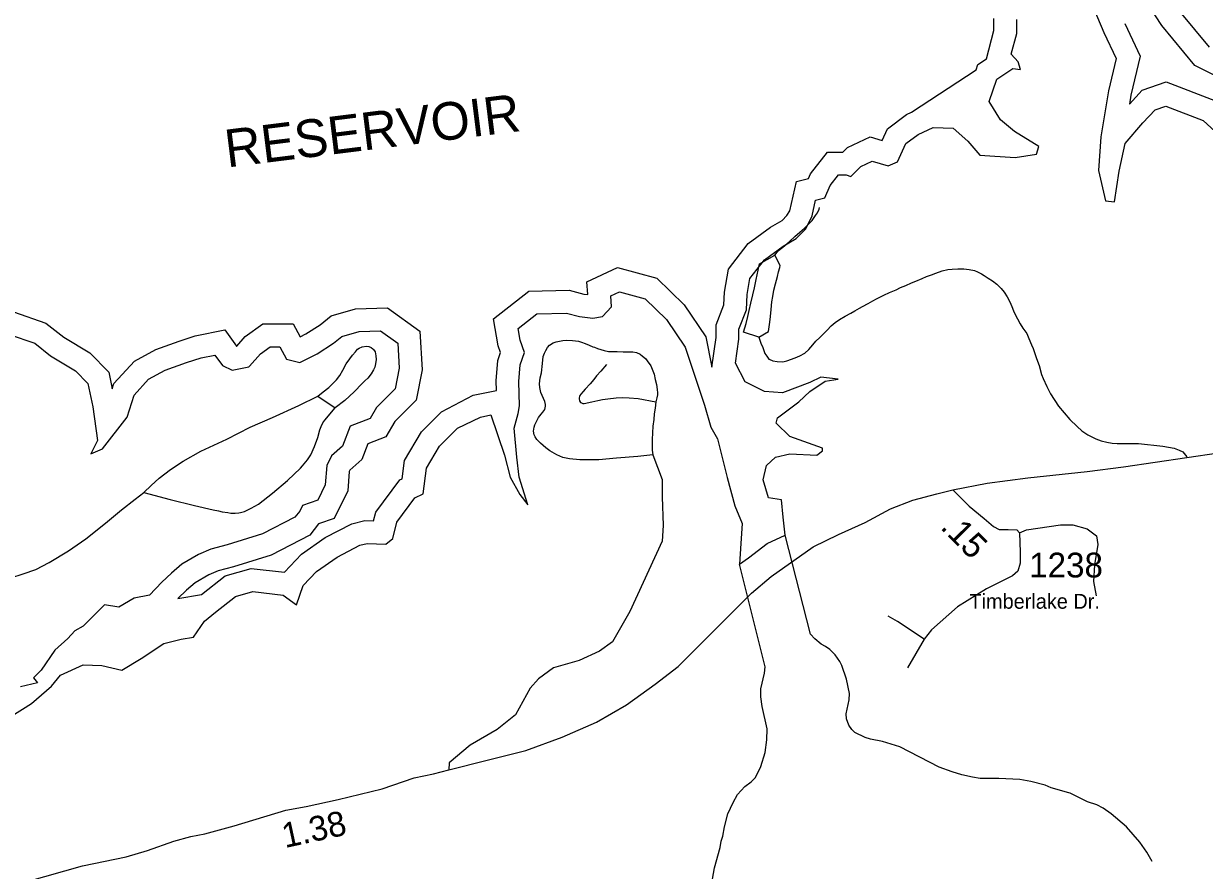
# Model space of a CAD drawing. Extents: x 1248089 to 1457196, y 820910 to 988753.
# Drawn here: x 1335904 to 1341854, y 869356 to 873625 of the extents above; entities that cross this region are included whole.
import ezdxf

# ---------------------------------------------------------------- set-up
doc = ezdxf.new("R2010")
doc.units = 0
for name, color, linetype in [('Exist Hydrographic Buffer Line', 7, 'Continuous'), ('Exist Hydrographic Misc Water Feature', 7, 'Continuous'), ('Exist Hydrographic Reservoir', 7, 'Continuous'), ('Exist Hydrographic Reservoir Label', 7, 'Continuous'), ('Exist Road Non-System Type 51', 7, 'Continuous'), ('Exist Road Primary NC Attributed', 7, 'Continuous'), ('Exist Road Secondary Type 51 Attributed', 7, 'Continuous'), ('Exist Road Secondary Type 51 Label', 7, 'Continuous'), ('Prop CMT Slope Fill', 7, 'Continuous'), ('Prop GRAU CAT1 Cell', 7, 'Continuous'), ('Prop Lane Lines', 7, 'Continuous')]:
    doc.layers.add(name, color=color, linetype=linetype)

msp = doc.modelspace()

# ---------------------------------------------------------------- linework, layer by layer
at = {"layer": 'Exist Hydrographic Buffer Line'}
for points in [[(1341452.9, 873625.9), (1341530.6, 873460.7), (1341483.6, 873263.5), (1341476.3, 873219.4), (1341541.4, 873288.6), (1341661.7, 873331.6), (1341910.1, 873235.2), (1341964.9, 873261.2), (1341994.8, 873346.7), (1341950.9, 873342), (1341806.6, 873414.2), (1341640.6, 873615.3), (1341493.7, 873840.3)], [(1339765.2, 872681.5), (1339798.8, 872829), (1339858.8, 872844), (1339869, 872867.4), (1339954.9, 872976.8), (1340032.5, 872976.8), (1340055.6, 872999.9), (1340170.6, 873053.6), (1340231, 873036.4), (1340257.6, 873094.5), (1340352.7, 873165.9), (1340378.8, 873177.6), (1340703.7, 873392.6), (1340712.5, 873418.1), (1340756.9, 873447.7), (1340793.8, 873590.1), (1340793.8, 873650.4)], [(1338010, 871667.1), (1338169, 871751.3), (1338286.6, 871774.8), (1338285.2, 871823.8), (1338293.8, 871927.4), (1338307, 871966.8), (1338295.5, 872001.2), (1338271.6, 872136.8), (1338450, 872275.6), (1338653.7, 872280.4), (1338727, 872261.1), (1338747.2, 872258.9), (1338743.2, 872323.5), (1338897.6, 872394.8), (1339095.2, 872341.4), (1339232.9, 872208), (1339342.3, 872045.8), (1339372.4, 871892.6), (1339393.8, 872042.7), (1339393.7, 872106.9), (1339433, 872206.9), (1339435.9, 872271.7), (1339456, 872387.2), (1339556.2, 872516.1), (1339667.9, 872599), (1339726.6, 872633), (1339750.6, 872657), (1339765.2, 872681.5)], [(1335853.3, 872172.7), (1336016.5, 872115.3), (1336106.2, 872045.1), (1336237.3, 871964.9), (1336333.9, 871868.3), (1336351.1, 871784.5), (1336359.4, 871810.8), (1336462.6, 871924), (1336571, 871982.8), (1336688.3, 872024.4), (1336769.2, 872051.4), (1336917.6, 872081.1), (1336977.4, 871999.5), (1336978.5, 871999.7), (1337020.5, 872047), (1337109.6, 872110.7), (1337262.7, 872110.7), (1337298.4, 872046.5), (1337325.9, 872060.8), (1337398.9, 872106.5), (1337453.5, 872152), (1337577.5, 872186.8), (1337738.3, 872191.9), (1337901.4, 872074.4), (1337912.2, 871879.8), (1337881.7, 871727), (1337774.4, 871619.6), (1337730.4, 871541.4), (1337638.9, 871506.6), (1337608.8, 871427.2), (1337548.6, 871374.5), (1337544.5, 871366.4), (1337537.6, 871268.9), (1337468.7, 871131), (1337391.1, 871102.8), (1337346.7, 871045.6), (1337151.8, 870946.1), (1336962, 870886.5), (1336884.9, 870867.2), (1336837.2, 870846), (1336768.5, 870805.9), (1336725.9, 870768.9), (1336681.3, 870727.5), (1336800.1, 870747.1), (1336919.6, 870842), (1337050.4, 870878.7), (1337218.2, 870859.6), (1337304.4, 870950.4), (1337424.5, 871034.5), (1337557.6, 871103.1), (1337623.1, 871120.1), (1337668.2, 871118.4), (1337679.3, 871162.7), (1337799.7, 871324.9), (1337811.6, 871330.8), (1337824, 871422.6), (1337909.4, 871566.4), (1338010, 871667.1)]]:
    msp.add_lwpolyline(points, dxfattribs=at)
at = {"layer": 'Exist Hydrographic Misc Water Feature'}
for points in [[(1340583.9, 869852.8), (1340517.3, 869876.2), (1340319.7, 869978.9), (1340232.3, 870006.9), (1340172.5, 870018.4), (1340144.6, 870027), (1340093.3, 870052.2), (1340077.6, 870066.5), (1340062.1, 870089), (1340050.8, 870121.2), (1340049.3, 870145.3), (1340065, 870216.8), (1340065.7, 870248.8), (1340051.4, 870321.2), (1340026.8, 870389.7), (1340017.3, 870410), (1339994, 870442.5), (1339966.7, 870469.2), (1339945, 870485.7), (1339923.3, 870496.2), (1339891.8, 870523), (1339870.4, 870547.5), (1339741.6, 871046.3)], [(1339376.2, 869312.4), (1339385.5, 869369.2), (1339413.9, 869472.5), (1339418.7, 869504.4), (1339427.2, 869528.2), (1339436.3, 869576), (1339453.8, 869641.5), (1339479.1, 869698.9), (1339502, 869738.4), (1339538.9, 869779.5), (1339571.4, 869802.6), (1339591.9, 869824.2), (1339619.2, 869879.5), (1339640.8, 869951), (1339650.3, 870014.8), (1339651.6, 870070.7), (1339626.1, 870183.3), (1339619.2, 870231.5), (1339620.1, 870271.5), (1339637.9, 870351.1), (1339640.6, 870382.9), (1339512.1, 870900.1)], [(1341590.9, 869400.6), (1341564, 869449.2), (1341529.1, 869498.1), (1341462.8, 869575.6), (1341384.3, 869641.6), (1341344.9, 869670.5), (1341313.3, 869687.2), (1341265.7, 869702.4), (1341178.6, 869746.5), (1341170.6, 869746.7), (1341083.2, 869772.7), (1341051.5, 869785.4), (1340979.9, 869805.1), (1340924.1, 869814.4), (1340818.1, 869818.9), (1340724.1, 869819.2), (1340685.6, 869826.7), (1340631.9, 869838), (1340583.9, 869852.8)]]:
    msp.add_lwpolyline(points, dxfattribs=at)
at = {"layer": 'Exist Hydrographic Reservoir'}
for points in [[(1341297.8, 873698.8), (1341347.9, 873579.3), (1341409.5, 873448.2), (1341371, 873286.2), (1341332.5, 873054.8), (1341320.9, 872885.2), (1341355.6, 872730.9), (1341401.8, 872727), (1341425, 872881.3), (1341455.8, 873020.1), (1341544.4, 873124.2), (1341606.1, 873189.8), (1341660, 873209.1), (1341848.8, 873135.8), (1341968.3, 873027.8)], [(1341879.7, 873506), (1341733.2, 873683.4)], [(1339877.2, 872656), (1339895.1, 872734.8), (1339941.4, 872746.3), (1339968.3, 872808), (1340010.7, 872862), (1340049.3, 872862), (1340072.4, 872854.3), (1340122.5, 872904.4), (1340180.3, 872931.4), (1340261.2, 872908.3), (1340307.5, 872927.6), (1340349.8, 873020.1), (1340411.5, 873066.4), (1340488.6, 873101.1), (1340588.8, 873097.3), (1340662, 873031.7), (1340723.6, 872962.3), (1340900.9, 872950.7), (1341008.8, 872966.1), (1341020.3, 873004.7), (1340897, 873081.8), (1340827.7, 873139.7), (1340769.9, 873232.2), (1340808.4, 873344.1), (1340889.3, 873398), (1340927.9, 873394.2), (1340916.3, 873432.7), (1340881.6, 873471.3), (1340908.6, 873575.4), (1340908.6, 873644.8)], [(1338091.2, 871585.9), (1338205.9, 871641.6), (1338258.1, 871652), (1338327.7, 871450.2), (1338355.5, 871338.8), (1338404.2, 871251.8), (1338445.9, 871199.6), (1338400.7, 871338.8), (1338390.3, 871439.7), (1338376.4, 871585.9), (1338397.2, 871659), (1338403.6, 871698.8), (1338400.2, 871820.6), (1338407.1, 871904.2), (1338428, 871966.8), (1338407.1, 872029.5), (1338396.7, 872088.6), (1338490.6, 872161.7), (1338640.1, 872165.2), (1338706.2, 872147.8), (1338772.3, 872140.8), (1338821, 872147.8), (1338866.2, 872196.5), (1338862.7, 872252.2), (1338907.9, 872273.1), (1339036.6, 872238.3), (1339144.4, 872133.9), (1339238.3, 871994.7), (1339335.6, 871702.3), (1339366.9, 871591), (1339401.7, 871531.8), (1339450.4, 871336.9), (1339488.7, 871194.2), (1339526, 871105.4), (1339519, 871004.5), (1339512.1, 870900.1), (1339557.3, 870931.4), (1339651.2, 871004.5), (1339741.6, 871046.3), (1339731.2, 871136.7), (1339724.2, 871223.7), (1339658.2, 871234.2), (1339630.3, 871324.7), (1339647.7, 871397.8), (1339692.9, 871439.5), (1339766, 871456.9), (1339901.6, 871450), (1339929.4, 871470.8), (1339929.4, 871484.8), (1339766, 871543.9), (1339696.4, 871610), (1339703.4, 871637.9), (1339811.2, 871717.9), (1339866.8, 871770.1), (1339943.3, 871822.3), (1340009.4, 871832.8), (1339922.5, 871843.2), (1339866.8, 871815.4), (1339727.7, 871763.2), (1339637.3, 871770.1), (1339539.9, 871818.9), (1339491.2, 871912.8), (1339508.6, 872034.6), (1339508.6, 872085.3), (1339546.8, 872182.7), (1339550.3, 872259.3), (1339564.2, 872339.3), (1339637.2, 872433.3), (1339731.1, 872502.9), (1339797.2, 872541.1), (1339845.9, 872589.9), (1339877.2, 872656)], [(1335831.9, 872058.5), (1335960.6, 872013.3), (1336040.6, 871950.6), (1336165.8, 871874.1), (1336228.4, 871811.4), (1336252.7, 871693.1), (1336277.1, 871522.6), (1336242.3, 871456.5), (1336301.4, 871480.8), (1336426.6, 871640.9), (1336461.4, 871752.3), (1336534.4, 871832.3), (1336617.9, 871877.5), (1336725.7, 871915.8), (1336798.7, 871940.2), (1336868.3, 871954.1), (1336906.5, 871901.9), (1336955.2, 871877.5), (1337038.7, 871894.9), (1337042.1, 871898.4), (1337097.8, 871961.1), (1337146.5, 871995.9), (1337195.2, 871995.9), (1337229.9, 871933.2), (1337296, 871915.8), (1337382.9, 871961.1), (1337466.4, 872013.3), (1337508.1, 872048.1), (1337595.1, 872072.4), (1337702.9, 872075.9), (1337789.8, 872013.3), (1337796.8, 871888), (1337775.9, 871783.6), (1337682, 871689.6), (1337650.7, 871633.9), (1337549.9, 871595.7), (1337511.6, 871494.7), (1337456, 871446), (1337431.6, 871397.3), (1337424.7, 871299.8), (1337386.4, 871223.3), (1337309.9, 871195.4), (1337296, 871167.6), (1337271.7, 871136.3), (1337108.2, 871052.8), (1336930.9, 870997.1), (1336847.4, 870976.2), (1336784.8, 870948.4), (1336701.3, 870899.6), (1336649.2, 870854.4), (1336600.5, 870809.1), (1336537.9, 870743), (1336461.4, 870729.1), (1336384.9, 870683.9), (1336311.8, 870694.3), (1336287.5, 870669.9), (1336204.3, 870588), (1336162.6, 870563.7), (1336127.8, 870525.4), (1336061.7, 870466.2), (1335992.2, 870365.3), (1335953.9, 870327), (1335974.8, 870302.6), (1335887.8, 870281.8)], [(1335839.1, 870132.1), (1335943.5, 870198.2), (1336044.3, 870285.2), (1336089.5, 870340.9), (1336204.3, 870393.1), (1336298.2, 870389.7), (1336399, 870365.3), (1336496.4, 870424.5), (1336611.2, 870501), (1336698.1, 870521.9), (1336760.7, 870532.3), (1336816.4, 870612.4), (1336872, 870657.6), (1336972.9, 870737.7), (1337059.8, 870762), (1337212.8, 870744.6), (1337278.9, 870695.9), (1337313.7, 870793.3), (1337379.7, 870863), (1337484.1, 870936), (1337598.8, 870995.2), (1337635.6, 871004.7), (1337729.5, 871001.2), (1337764.3, 871029.1), (1337785.2, 871112.6), (1337875.6, 871234.4), (1337917.3, 871255.3), (1337934.7, 871384.1), (1338000.8, 871495.4), (1338091.2, 871585.9)]]:
    msp.add_lwpolyline(points, dxfattribs=at)
at = {"layer": 'Exist Road Non-System Type 51'}
msp.add_line((1337386.9, 871747.2), (1337473.7, 871687.4), dxfattribs=at)
for points in [[(1339690.3, 872457.8), (1339708.7, 872481.4), (1339739.2, 872504.8), (1339763.7, 872526.3), (1339790.2, 872551.8), (1339816.7, 872573.3), (1339839.1, 872592.9), (1339857.5, 872612.5), (1339877.9, 872632.1), (1339894.4, 872657.8), (1339904.7, 872671.6), (1339913, 872689.4), (1339915.2, 872697.4)], [(1339609.9, 872045.1), (1339532.4, 872068.7), (1339545.2, 872112.5), (1339554, 872148.3), (1339560.6, 872178.2), (1339569.3, 872216), (1339578.2, 872257.9), (1339586.9, 872293.7), (1339595.8, 872335.6), (1339606.7, 872381.4), (1339613.3, 872413.3), (1339690.3, 872457.8)], [(1339609.9, 872045.1), (1339658.5, 872072.2), (1339665.5, 872120.1), (1339668, 872148), (1339670.8, 872184), (1339675.5, 872221.9), (1339680.1, 872249.8), (1339684.7, 872281.8), (1339693.4, 872313.6), (1339704.1, 872349.4), (1339708.6, 872373.3), (1339715, 872395.2), (1339717.2, 872405.2), (1339690.3, 872457.8)], [(1339609.9, 872045.1), (1339621.2, 872008.9), (1339627, 871996.7), (1339640.3, 871962.5), (1339650, 871948.3), (1339659.7, 871934), (1339673.6, 871927.8), (1339679.6, 871925.6), (1339701.5, 871921.2), (1339729.5, 871920.6), (1339749.6, 871924.2), (1339791.9, 871939.4), (1339816.2, 871950.9), (1339840.5, 871964.4), (1339860.8, 871982), (1339881.3, 872005.6), (1339895.7, 872023.4), (1339916.1, 872043), (1339934.5, 872060.6), (1339952.9, 872080.3), (1339973.3, 872101.9), (1339993.6, 872117.5), (1340016, 872133), (1340044.3, 872150.5), (1340072.6, 872165.9), (1340092.9, 872177.5), (1340117.2, 872191), (1340131.3, 872198.7), (1340159.7, 872214.2), (1340184, 872227.7), (1340202.2, 872237.3), (1340238.6, 872256.6), (1340266.9, 872270.1), (1340301.1, 872283.4), (1340323.4, 872294.9), (1340349.6, 872304.4), (1340377.9, 872317.9), (1340400.1, 872327.4), (1340432.4, 872340.8), (1340454.6, 872350.3), (1340478.8, 872357.9), (1340501, 872367.4), (1340533.2, 872378.8), (1340561.4, 872386.2), (1340583.4, 872387.8), (1340611.5, 872389.2), (1340641.5, 872388.6), (1340669.4, 872386.1), (1340695.3, 872379.5), (1340711.2, 872373.2), (1340731, 872362.8), (1340744.9, 872354.5), (1340764.6, 872342.1), (1340786.3, 872327.7), (1340808, 872311.2), (1340829.6, 872288.8), (1340845.2, 872270.4), (1340860.8, 872248.1), (1340874.3, 872221.8), (1340883.8, 872199.6), (1340893.4, 872177.4), (1340903, 872155.2), (1340912.6, 872137), (1340926.1, 872110.7), (1340939.7, 872090.4), (1340959.1, 872062), (1340970.6, 872037.8), (1340984, 872005.5), (1340991.6, 871987.3), (1340997.3, 871971.2), (1341008.6, 871937), (1341021.9, 871900.7), (1341034.1, 871855.6), (1341042.9, 871835.9), (1341060.1, 871795.5), (1341079.4, 871759.1), (1341120.1, 871696.3), (1341176.8, 871629.1), (1341214.1, 871594.3), (1341237.7, 871571.8), (1341267.3, 871551.2), (1341306.9, 871532.4), (1341334.8, 871521.8), (1341362.6, 871515.3), (1341390.6, 871510.7), (1341414.5, 871508.2), (1341444.5, 871507.6), (1341522.6, 871508.1), (1341644.4, 871495.6), (1341702.2, 871484.5), (1341728, 871473.9), (1341745.9, 871465.6), (1341765.4, 871441.2)], [(1337386.9, 871747.2), (1337413.3, 871768.7), (1337441.8, 871790.1), (1337466.3, 871813.6), (1337480.6, 871829.4), (1337497, 871851), (1337513.6, 871878.7), (1337530.3, 871910.4), (1337547.9, 871935.3), (1337561.9, 871953.1), (1337577.2, 871969.9), (1337587.4, 871983.7), (1337595.6, 871989.5), (1337609.7, 871995.3), (1337631.8, 871998.8), (1337643.7, 871996.6), (1337655.7, 871992.3), (1337663.5, 871986.2), (1337667.5, 871982.1), (1337675.2, 871969.9), (1337678.8, 871949.9), (1337680.8, 871931.4), (1337678.3, 871909.4), (1337674, 871893.5), (1337667.7, 871879.6), (1337655.3, 871859.9), (1337638.9, 871838.2), (1337624.6, 871824.5), (1337610.3, 871810.7), (1337569.5, 871769.5), (1337522.5, 871724.5), (1337473.7, 871687.4)], [(1339075.7, 871451), (1338999.7, 871442.7), (1338891.5, 871434.8), (1338803.3, 871426.6), (1338759.3, 871425.5), (1338707.2, 871426.5), (1338655.3, 871431.6), (1338621.4, 871438.2), (1338591.7, 871450.8), (1338556.1, 871471.6), (1338536.3, 871486), (1338508.8, 871510.5), (1338491.2, 871528.9), (1338481.4, 871541.1), (1338477.6, 871551.2), (1338474, 871571.3), (1338476.4, 871591.2), (1338480.7, 871603.2), (1338499.4, 871638.8), (1338511.8, 871656.6), (1338520, 871666.4), (1338530.2, 871680.2), (1338534.6, 871696.1), (1338534.7, 871704.1), (1338531, 871720.2), (1338517.6, 871750.5), (1338509.9, 871764.7), (1338506.4, 871790.8), (1338504.8, 871808.8), (1338507.4, 871838.8), (1338513.9, 871864.7), (1338518.8, 871910.9), (1338523.3, 871946.9), (1338529.6, 871962.8), (1338535.9, 871976.7), (1338544.2, 871992.5), (1338554.5, 872004.3), (1338572.7, 872015.9), (1338588.8, 872021.6), (1338621, 872027), (1338641, 872028.6), (1338671, 872028), (1338700.9, 872023.4), (1338714.9, 872019.1), (1338734.7, 872012.7), (1338754.6, 872004.3), (1338772.4, 871995.9), (1338780.4, 871993.8), (1338796.3, 871987.4), (1338830.1, 871976.7), (1338852, 871972.3), (1338872, 871971.9), (1338896, 871971.4), (1338926, 871970.8), (1338942, 871970.5), (1338968, 871970), (1338974, 871969.8), (1338992, 871967.5), (1339011.8, 871959.1), (1339023.6, 871948.8), (1339037.4, 871936.6), (1339047.2, 871924.3), (1339065.5, 871899.3), (1339082.1, 871857.2), (1339087.6, 871831.1), (1339093.1, 871805), (1339096.6, 871780.9), (1339098.2, 871762.9), (1339098, 871752.9), (1339095.8, 871738.9), (1339089.4, 871719)], [(1338841, 871906.2), (1338812.3, 871872.7), (1338791.8, 871849.1), (1338777.4, 871831.3), (1338759, 871809.7), (1338734.4, 871782.2), (1338724.2, 871770.4), (1338711.9, 871756.6), (1338707.8, 871750.7), (1338705.7, 871746.7), (1338703.5, 871736.8), (1338703.4, 871732.8), (1338705.2, 871722.7), (1338711, 871714.6), (1338715, 871712.5), (1338723, 871710.4), (1338725, 871710.3), (1338729, 871710.2), (1338767.1, 871717.5), (1338797.3, 871724.9), (1338821.4, 871730.4), (1338847.5, 871733.9), (1338889.6, 871739), (1338923.7, 871740.4), (1338955.7, 871737.7), (1339001.6, 871734.8), (1339089.4, 871719)], [(1336510.6, 871260.5), (1336547.3, 871295.8), (1336588.1, 871333), (1336645, 871377.9), (1336707.9, 871418.6), (1336796.9, 871468.9), (1336928.3, 871530.3), (1337045.5, 871589.9), (1337158.6, 871639.7), (1337291.9, 871699.1), (1337386.9, 871747.2)], [(1339089.4, 871719), (1339086.7, 871687.1), (1339082.1, 871657.1), (1339079.5, 871629.2), (1339074.9, 871595.2), (1339071.5, 871529.3), (1339072.4, 871475.2), (1339075.7, 871451)], [(1336510.6, 871260.5), (1336642, 871225.8), (1336765.4, 871195.3), (1336859, 871173.4), (1336887, 871168.9), (1336904.9, 871164.5), (1336932.8, 871160), (1336948.8, 871157.6), (1336970.8, 871157.2), (1336988.8, 871158.8), (1336996.9, 871160.7), (1337017, 871166.3), (1337051.3, 871181.6), (1337087.8, 871202.9), (1337158.9, 871257.5), (1337234.3, 871322), (1337299.6, 871384.7), (1337309.8, 871396.5), (1337334.4, 871426.1), (1337350.9, 871451.7), (1337369.8, 871493.4), (1337386.7, 871539.1), (1337397.5, 871576.9), (1337403.8, 871594.8), (1337412.2, 871612.6), (1337422.5, 871626.4), (1337473.7, 871687.4)], [(1339075.7, 871451), (1339122.8, 871327.6), (1339122.8, 871239.1), (1339127.5, 871094.8), (1339122.8, 871015.7), (1338960, 870661.9), (1338871.6, 870508.3), (1338806.5, 870461.8), (1338704.2, 870415.2), (1338573.9, 870378), (1338499.5, 870322.1), (1338457.6, 870275.6), (1338383.2, 870140.6), (1338290.2, 870066.1), (1338155.3, 869987), (1338048.3, 869898.5), (1338047.1, 869863.2)], [(1335329.2, 870925.7), (1335383.1, 870881.3), (1335428.7, 870862.4), (1335482.4, 870843.3), (1335520.2, 870832.5), (1335553.6, 870824.2), (1335570.2, 870819.4), (1335595, 870812.4), (1335610.9, 870808.3), (1335630.9, 870805.9), (1335670.9, 870805.1), (1335763.1, 870811.2), (1335797.3, 870818.5), (1335839.6, 870831.7), (1335902, 870850.5), (1335966.5, 870873.2), (1336033.2, 870907.9), (1336130.5, 870967.9), (1336217.7, 871028.2), (1336317.4, 871106.3), (1336396.8, 871174.7), (1336465.9, 871227.4), (1336510.6, 871260.5)], [(1340923.4, 871057.8), (1340957.3, 871072.9), (1341129.2, 871098.6), (1341191.4, 871098.6), (1341264.5, 871078.4), (1341310.2, 871043.7), (1341317.5, 870999.7), (1341301.1, 870897.3), (1341295.6, 870813.1), (1341308.4, 870739.9)], [(1340756.8, 870776.3), (1340610.2, 870685.2), (1340480, 870568.8), (1340442.7, 870522.3), (1340359, 870378)], [(1340442.7, 870522.3), (1340307.8, 870610.7), (1340261.3, 870638.6)]]:
    msp.add_lwpolyline(points, dxfattribs=at)
at = {"layer": 'Exist Road Primary NC Attributed'}
for points in [[(1340587.3, 871274.3), (1340760.4, 871309), (1340965, 871335.3), (1341263.2, 871367.5), (1341447.3, 871390.9), (1342084.5, 871484.5), (1342259.9, 871513.8), (1342355.2, 871525.3), (1342483.8, 871531.1), (1342679.6, 871560.4), (1342913.5, 871618.9), (1343144.4, 871680.3), (1343316.8, 871738.8), (1343444.4, 871793.6), (1343573.1, 871860.9), (1343666.6, 871934), (1343775.9, 872024.4)], [(1335921.5, 869299.9), (1336200.6, 869378.9), (1336420.5, 869425.2), (1336528.7, 869456), (1336661.6, 869504.2), (1336746.4, 869527.6), (1336818, 869540.8), (1336965.6, 869580.3), (1337225, 869660.2), (1337328.7, 869679.2), (1337489.5, 869714.3), (1337711.6, 869768.4), (1337871.7, 869823.7), (1337969.6, 869842.7), (1338047.1, 869863.2), (1338240, 869911.4), (1338434.4, 869961.1), (1338618.8, 870028.3), (1338791.3, 870102.9), (1338941.8, 870190.6), (1339086.5, 870294.5), (1339203.1, 870384.3), (1339396, 870577.4), (1339572.8, 870754.4), (1339670.7, 870837.8), (1339883.3, 870987.3), (1340010.5, 871048.8), (1340144.9, 871110.2), (1340273.5, 871178.9), (1340386.1, 871222.8), (1340505.9, 871255), (1340587.3, 871274.3)]]:
    msp.add_lwpolyline(points, dxfattribs=at)
at = {"layer": 'Exist Road Secondary Type 51 Attributed'}
msp.add_lwpolyline([(1340587.3, 871274.3), (1340669.1, 871192.4), (1340745.1, 871130.9), (1340791.9, 871089.3), (1340821.1, 871075.4), (1340865, 871075.4), (1340908.8, 871072.4), (1340923.4, 871057.8), (1340926.3, 870961.3), (1340926.3, 870905.7), (1340914.6, 870864.7), (1340888.3, 870841.3), (1340756.8, 870776.3)], dxfattribs=at)

# ---------------------------------------------------------------- texts
at = {"layer": 'Exist Hydrographic Reservoir Label'}
msp.add_text('RESERVOIR', height=190, rotation=7.08296, dxfattribs=at).set_placement((1336930.4, 872899.3))
at = {"layer": 'Exist Road Secondary Type 51 Label'}
msp.add_text('Timberlake Dr.', height=75, dxfattribs=at).set_placement((1340670.6, 870675.3))
at = {"layer": 'Prop CMT Slope Fill'}
msp.add_text('1.38', height=125, rotation=12.31758, dxfattribs=at).set_placement((1337221.3, 869468.7))
at = {"layer": 'Prop GRAU CAT1 Cell'}
msp.add_text('.15', height=125, rotation=314.97589, dxfattribs=at).set_placement((1340519.4, 871082.1))
at = {"layer": 'Prop Lane Lines'}
msp.add_text('1238', height=125, dxfattribs=at).set_placement((1340971.5, 870833))

doc.saveas('drawing.dxf')
